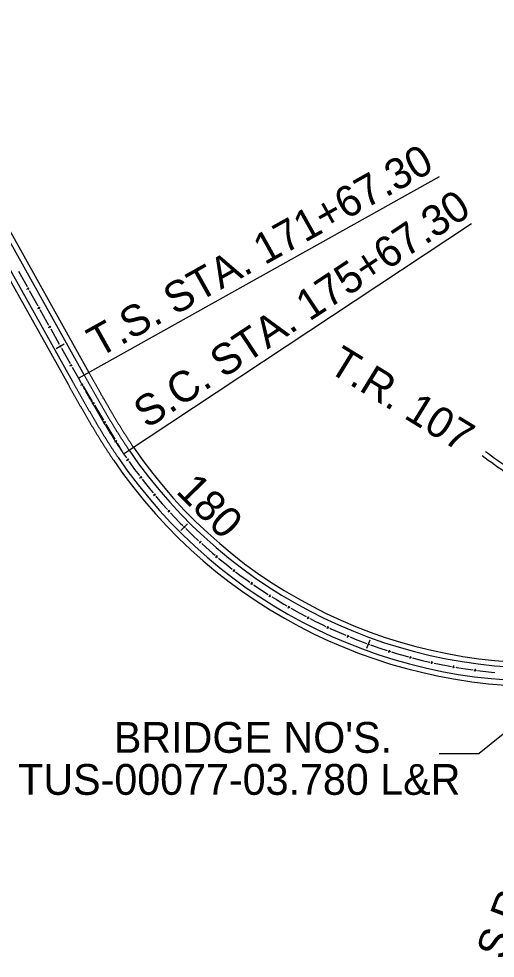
# Model space of a CAD drawing. Extents: x 0 to 34000, y 0 to 22000.
# Drawn here: x 23261 to 25424, y 4486 to 8756 of the extents above; entities that cross this region are included whole.
import ezdxf

# ---------------------------------------------------------------- set-up
doc = ezdxf.new("R2010")
doc.units = 0
doc.layers.add('Default', color=7, linetype='Continuous')
doc.layers.add('GE_P_CL_100', color=7, linetype='Continuous')

msp = doc.modelspace()

# ---------------------------------------------------------------- linework, layer by layer
at = {"layer": 'Default'}
for p, q in [((22679.2, 8756.5), (23578.5, 7148.4)), ((22605.9, 8715.4), (23505.2, 7107.4)), ((22658.3, 8744.7), (23557.6, 7136.7)), ((22585, 8703.7), (23484.3, 7095.7)), ((23297.9, 7527.2), (23308.4, 7533.1)), ((23346.7, 7440), (23357.2, 7445.8)), ((23395.5, 7352.7), (23406, 7358.5)), ((23430.6, 7257.7), (23467.2, 7278.2)), ((23493.2, 7178.1), (23503.6, 7184)), ((23542.9, 7091.2), (23553.2, 7097.3)), ((23594.2, 7005.4), (23604.5, 7011.5)), ((23645.5, 6919.5), (23655.8, 6925.7)), ((23696.8, 6833.7), (23707.1, 6839.9)), ((23750.3, 6748.7), (23760.1, 6755.7)), ((23809.6, 6667.9), (23819.1, 6675.2)), ((23872.4, 6589.8), (23881.6, 6597.5)), ((23938.5, 6514.3), (23947.2, 6522.5)), ((23943, 6518.3), (23943, 6518.3)), ((23996.5, 6430.7), (24026.9, 6461)), ((24012.2, 6446.2), (24012.2, 6446.2)), ((24080.4, 6372.7), (24088.4, 6381.6)), ((24155.7, 6306.7), (24163.4, 6315.9)), ((24233.9, 6244), (24241.2, 6253.5)), ((24314.8, 6184.8), (24321.7, 6194.6)), ((24398.2, 6129), (24404.6, 6139.2)), ((24483.9, 6077.1), (24489.9, 6087.5)), ((24571.9, 6029), (24577.4, 6039.6)), ((24661.7, 5984.6), (24666.8, 5995.4)), ((24753.6, 5944.3), (24758.1, 5955.4)), ((24842.1, 5894.7), (24856.3, 5933.3)), ((24942, 5875.8), (24945.5, 5887.3)), ((25038.2, 5847.9), (25041.3, 5859.5)), ((25135.6, 5824), (25138.2, 5835.8)), ((25233.9, 5804.6), (25236, 5816.4)), ((25333.1, 5789.3), (25334.5, 5801.2))]:
    msp.add_line(p, q, dxfattribs=at)
for points in [[(23259.2, 7608.7), (23298.3, 7538.9)], [(23300.7, 7534.5), (23305.6, 7525.8)], [(23308, 7521.5), (23347.1, 7451.6)], [(23349.5, 7447.3), (23354.4, 7438.5)], [(23356.8, 7434.2), (23395.9, 7364.4)], [(23398.3, 7360), (23403.2, 7351.3)], [(23405.6, 7346.9), (23444.7, 7277.1)], [(23447.1, 7272.7), (23452, 7264)], [(23454.5, 7259.6), (23493.5, 7189.8)], [(23495.9, 7185.4), (23500.8, 7176.7)], [(23503.3, 7172.3), (23531.4, 7122.1), (23542.9, 7102.9)], [(23545.4, 7098.6), (23550.6, 7090)], [(23553.1, 7085.7), (23594.2, 7017)], [(23596.8, 7012.7), (23601.9, 7004.2)], [(23604.5, 6999.9), (23645.5, 6931.2)], [(23648.1, 6926.9), (23653.2, 6918.3)], [(23655.8, 6914), (23696.9, 6845.4)], [(23699.4, 6841.1), (23704.6, 6832.5)], [(23707.1, 6828.2), (23736.6, 6778.9), (23740.7, 6772.8), (23749.4, 6760.4)], [(23752.3, 6756.3), (23758.1, 6748.1)], [(23761, 6744), (23763.7, 6740.2), (23786.9, 6707.8), (23808.3, 6679.5)], [(23811.3, 6675.5), (23817.4, 6667.6)], [(23820.5, 6663.7), (23835.6, 6644.1), (23860.6, 6613.1), (23870.6, 6601.3)], [(23873.8, 6597.5), (23880.2, 6589.8)], [(23883.4, 6586), (23886.4, 6582.4), (23912.5, 6552.2), (23936.1, 6525.8)], [(23939.4, 6522), (23946.2, 6514.8)], [(23949.7, 6511.1), (23966.5, 6493.1), (23994.3, 6464.1), (24005, 6453.4)], [(24008.5, 6449.8), (24016, 6442.3)], [(24019.1, 6439.2), (24022.5, 6435.8), (24051.3, 6408), (24077, 6384)], [(24080.7, 6380.6), (24088.1, 6373.8)], [(24091.8, 6370.5), (24110.1, 6353.9), (24140.1, 6327.5), (24151.9, 6317.7)], [(24155.7, 6314.5), (24163.4, 6308.1)], [(24167.2, 6304.9), (24170.8, 6301.9), (24201.8, 6276.6), (24229.6, 6254.8)], [(24233.6, 6251.8), (24241.5, 6245.7)], [(24245.5, 6242.7), (24265.3, 6227.7), (24297.6, 6204.2), (24310.1, 6195.4)], [(24314.2, 6192.6), (24322.3, 6186.8)], [(24326.4, 6183.9), (24330.3, 6181.2), (24363.3, 6158.8), (24393, 6139.5)], [(24397.2, 6136.8), (24405.6, 6131.5)], [(24409.9, 6128.8), (24430.7, 6115.8), (24465, 6094.9), (24478.2, 6087.3)], [(24482.6, 6084.8), (24491.2, 6079.8)], [(24495.6, 6077.3), (24499.6, 6075), (24534.6, 6055.4), (24565.7, 6038.9)], [(24570.2, 6036.6), (24579.1, 6032)], [(24583.5, 6029.7), (24605.5, 6018.4), (24641.3, 6000.8), (24655.2, 5994.3)], [(24659.7, 5992.1), (24668.8, 5987.9)], [(24673.3, 5985.8), (24677.6, 5983.8), (24714.2, 5967.6), (24746.6, 5953.7)], [(24751.2, 5951.7), (24760.5, 5948)], [(24765.1, 5946.1), (24788, 5936.8), (24825.2, 5922.3), (24839.6, 5917)], [(24844.3, 5915.3), (24853.7, 5911.9)], [(24858.4, 5910.1), (24862.8, 5908.5), (24900.7, 5895.6), (24934.2, 5884.6)], [(24938.9, 5883), (24948.5, 5880.1)], [(24953.3, 5878.6), (24976.8, 5871.3), (25015.4, 5860.3), (25030.1, 5856.3)], [(25034.9, 5855), (25044.6, 5852.4)], [(25049.4, 5851.1), (25053.9, 5849.8), (25092.6, 5840), (25127.1, 5832.1)], [(25132, 5831), (25141.8, 5828.8)], [(25146.6, 5827.8), (25170.9, 5822.5), (25210.1, 5814.9), (25225.1, 5812.3)], [(25230, 5811.4), (25239.9, 5809.7)], [(25244.8, 5808.8), (25249.4, 5808), (25289, 5801.5), (25323.9, 5796.6)], [(25328.8, 5795.9), (25338.7, 5794.7)], [(25343.7, 5794.1), (25368.2, 5791.1), (25408, 5786.6), (25423.2, 5785.3)]]:
    msp.add_lwpolyline(points, dxfattribs=at)
for radius, end in [(2261.8, 274.1413), (2237.8, 274.1413), (2345.8, 273.5817), (2321.8, 273.857)]:
    msp.add_arc((25631.8, 8067.6), radius, 214.2163, end, dxfattribs=at)
for points in [[(23557.6, 7136.7), (23560.6, 7131.3), (23563.6, 7126), (23566.6, 7120.6), (23569.6, 7115.2), (23572.6, 7109.9), (23575.6, 7104.5), (23578.6, 7099.1), (23581.6, 7093.8), (23584.6, 7088.4), (23587.6, 7083.1), (23590.6, 7077.7), (23593.6, 7072.4), (23596.6, 7067), (23599.7, 7061.7), (23602.7, 7056.3), (23605.7, 7051), (23608.7, 7045.7), (23611.8, 7040.3), (23614.8, 7035), (23617.8, 7029.7), (23620.9, 7024.3), (23623.9, 7019), (23626.9, 7013.7), (23630, 7008.4), (23633, 7003.1), (23636.1, 6997.8), (23639.2, 6992.5), (23642.2, 6987.2), (23645.3, 6981.9), (23648.4, 6976.6), (23651.5, 6971.3), (23654.6, 6966.1), (23657.7, 6960.8), (23660.8, 6955.5), (23663.9, 6950.3), (23667, 6945), (23670.1, 6939.8), (23673.3, 6934.5), (23676.4, 6929.3), (23679.6, 6924.1), (23682.7, 6918.8), (23685.9, 6913.6), (23689.1, 6908.4), (23692.3, 6903.2), (23695.4, 6898), (23698.6, 6892.8), (23701.9, 6887.6), (23705.1, 6882.5), (23708.3, 6877.3), (23711.5, 6872.1), (23714.8, 6867), (23718.1, 6861.9), (23721.3, 6856.7), (23724.6, 6851.6), (23727.9, 6846.5), (23731.2, 6841.4), (23734.5, 6836.2), (23737.8, 6831.2), (23741.2, 6826.1), (23744.5, 6821), (23747.9, 6815.9), (23751.3, 6810.9), (23754.6, 6805.8), (23758, 6800.8), (23761.4, 6795.8)], [(23578.5, 7148.4), (23581.5, 7143), (23584.5, 7137.7), (23587.5, 7132.3), (23590.5, 7127), (23593.5, 7121.6), (23596.5, 7116.2), (23599.5, 7110.9), (23602.5, 7105.5), (23605.5, 7100.2), (23608.5, 7094.8), (23611.5, 7089.5), (23614.5, 7084.1), (23617.6, 7078.8), (23620.6, 7073.5), (23623.6, 7068.1), (23626.6, 7062.8), (23629.6, 7057.5), (23632.6, 7052.2), (23635.6, 7046.9), (23638.7, 7041.6), (23641.7, 7036.2), (23644.7, 7030.9), (23647.8, 7025.7), (23650.8, 7020.4), (23653.8, 7015.1), (23656.9, 7009.8), (23659.9, 7004.5), (23663, 6999.3), (23666.1, 6994), (23669.1, 6988.7), (23672.2, 6983.5), (23675.3, 6978.2), (23678.4, 6973), (23681.4, 6967.7), (23684.5, 6962.5), (23687.6, 6957.3), (23690.8, 6952.1), (23693.9, 6946.9), (23697, 6941.7), (23700.1, 6936.5), (23703.3, 6931.3), (23706.4, 6926.1), (23709.6, 6920.9), (23712.7, 6915.8), (23715.9, 6910.6), (23719.1, 6905.4), (23722.3, 6900.3), (23725.4, 6895.2), (23728.6, 6890), (23731.9, 6884.9), (23735.1, 6879.8), (23738.3, 6874.7), (23741.6, 6869.6), (23744.8, 6864.5), (23748.1, 6859.5), (23751.3, 6854.4), (23754.6, 6849.3), (23757.9, 6844.3), (23761.2, 6839.3), (23764.5, 6834.2), (23767.9, 6829.2), (23771.2, 6824.2), (23774.6, 6819.2), (23777.9, 6814.2), (23781.3, 6809.3)], [(23484.3, 7095.7), (23487.3, 7090.3), (23490.3, 7085), (23493.3, 7079.6), (23496.3, 7074.2), (23499.3, 7068.8), (23502.3, 7063.4), (23505.3, 7058.1), (23508.3, 7052.7), (23511.4, 7047.3), (23514.4, 7041.9), (23517.4, 7036.5), (23520.4, 7031.1), (23523.5, 7025.8), (23526.5, 7020.4), (23529.6, 7015), (23532.6, 7009.6), (23535.7, 7004.2), (23538.7, 6998.8), (23541.8, 6993.4), (23544.8, 6988.1), (23547.9, 6982.7), (23551, 6977.3), (23554.1, 6971.9), (23557.2, 6966.5), (23560.3, 6961.1), (23563.4, 6955.8), (23566.5, 6950.4), (23569.6, 6945), (23572.7, 6939.6), (23575.9, 6934.3), (23579, 6928.9), (23582.2, 6923.5), (23585.3, 6918.2), (23588.5, 6912.8), (23591.6, 6907.4), (23594.8, 6902.1), (23598, 6896.7), (23601.2, 6891.4), (23604.4, 6886), (23607.7, 6880.7), (23610.9, 6875.3), (23614.1, 6870), (23617.4, 6864.7), (23620.6, 6859.3), (23623.9, 6854), (23627.2, 6848.7), (23630.5, 6843.3), (23633.8, 6838), (23637.1, 6832.7), (23640.4, 6827.4), (23643.8, 6822.1), (23647.1, 6816.8), (23650.5, 6811.5), (23653.9, 6806.2), (23657.3, 6801), (23660.7, 6795.7), (23664.1, 6790.4), (23667.5, 6785.2), (23671, 6779.9), (23674.5, 6774.7), (23677.9, 6769.4), (23681.4, 6764.2), (23684.9, 6759), (23688.4, 6753.7), (23692, 6748.5)], [(23505.2, 7107.4), (23508.2, 7102), (23511.2, 7096.7), (23514.2, 7091.3), (23517.2, 7085.9), (23520.2, 7080.6), (23523.2, 7075.2), (23526.3, 7069.8), (23529.3, 7064.4), (23532.3, 7059.1), (23535.3, 7053.7), (23538.3, 7048.3), (23541.4, 7042.9), (23544.4, 7037.6), (23547.4, 7032.2), (23550.5, 7026.8), (23553.5, 7021.4), (23556.5, 7016.1), (23559.6, 7010.7), (23562.6, 7005.3), (23565.7, 6999.9), (23568.8, 6994.6), (23571.8, 6989.2), (23574.9, 6983.9), (23578, 6978.5), (23581.1, 6973.1), (23584.2, 6967.8), (23587.3, 6962.4), (23590.4, 6957.1), (23593.5, 6951.7), (23596.6, 6946.4), (23599.7, 6941), (23602.8, 6935.7), (23606, 6930.3), (23609.1, 6925), (23612.3, 6919.7), (23615.5, 6914.3), (23618.6, 6909), (23621.8, 6903.7), (23625, 6898.4), (23628.2, 6893.1), (23631.4, 6887.8), (23634.6, 6882.5), (23637.9, 6877.2), (23641.1, 6871.9), (23644.4, 6866.6), (23647.6, 6861.3), (23650.9, 6856), (23654.2, 6850.7), (23657.5, 6845.5), (23660.8, 6840.2), (23664.1, 6834.9), (23667.4, 6829.7), (23670.7, 6824.4), (23674.1, 6819.2), (23677.5, 6814), (23680.8, 6808.7), (23684.2, 6803.5), (23687.6, 6798.3), (23691, 6793.1), (23694.5, 6787.9), (23697.9, 6782.7), (23701.4, 6777.5), (23704.8, 6772.4), (23708.3, 6767.2), (23711.8, 6762)], [(23531.4, 7122.1), (23534.4, 7116.7), (23537.4, 7111.3), (23540.4, 7105.9), (23543.4, 7100.6), (23546.4, 7095.2), (23549.4, 7089.8), (23552.4, 7084.5), (23555.4, 7079.1), (23558.4, 7073.7), (23561.5, 7068.4), (23564.5, 7063), (23567.5, 7057.6), (23570.5, 7052.3), (23573.5, 7046.9), (23576.6, 7041.6), (23579.6, 7036.2), (23582.6, 7030.9), (23585.7, 7025.5), (23588.7, 7020.2), (23591.8, 7014.8), (23594.8, 7009.5), (23597.9, 7004.1), (23600.9, 6998.8), (23604, 6993.4), (23607.1, 6988.1), (23610.1, 6982.8), (23613.2, 6977.5), (23616.3, 6972.1), (23619.4, 6966.8), (23622.5, 6961.5), (23625.6, 6956.2), (23628.7, 6950.9), (23631.8, 6945.6), (23635, 6940.3), (23638.1, 6935), (23641.2, 6929.7), (23644.4, 6924.4), (23647.5, 6919.1), (23650.7, 6913.8), (23653.9, 6908.6), (23657.1, 6903.3), (23660.3, 6898), (23663.5, 6892.8), (23666.7, 6887.5), (23669.9, 6882.3), (23673.1, 6877.1), (23676.4, 6871.8), (23679.6, 6866.6), (23682.9, 6861.4), (23686.2, 6856.2), (23689.4, 6851), (23692.7, 6845.8), (23696, 6840.6), (23699.4, 6835.4), (23702.7, 6830.2), (23706, 6825), (23709.4, 6819.9), (23712.7, 6814.7), (23716.1, 6809.6), (23719.5, 6804.4), (23722.9, 6799.3), (23726.3, 6794.2), (23729.7, 6789.1), (23733.2, 6784), (23736.6, 6778.9)], [(26192.3, 6596.8), (26175.7, 6598.4), (26119.8, 6605.9), (26063.9, 6599.1), (26035.2, 6580.5), (26005.8, 6562.4), (25957.9, 6553.3), (25768.1, 6559.3), (25598, 6618.1), (25364.7, 6769.6)], [(26239.1, 6618.9), (26219.5, 6618.3), (26178.5, 6622.2), (26119.9, 6630), (26055.5, 6622.2), (26022.3, 6600.8), (25997, 6585.2), (25956, 6577.4), (25772.5, 6583.2), (25608.6, 6639.8), (25380.3, 6788.1)]]:
    msp.add_spline(points, degree=3, dxfattribs=at)
at = {"layer": 'GE_P_CL_100'}
for p, q in [((23531.4, 7122.1), (25171.2, 8039.1)), ((23736.6, 6778.9), (25317, 7825.2)), ((25802.5, 5779.9), (25351.3, 5416.6)), ((25169.1, 5416.6), (25351.3, 5416.6))]:
    msp.add_line(p, q, dxfattribs=at)

# ---------------------------------------------------------------- texts
for s, rotation, p in [('T.S. STA. 171+67.30', 29.2166, (23623.8, 7213.9)), ('S.C. STA. 175+67.30', 33.5066, (23843.1, 6890.5)), ('T.R. 107', 328.4259, (24658.9, 7156.7)), ('180', 314.8013, (23970, 6604.6)), ('S.R. 258', 69.1419, (25465.2, 4471.6))]:
    msp.add_text(s, height=140, rotation=rotation, dxfattribs=at).set_placement(p)
for s, p in [("BRIDGE NO'S.", (23692.7, 5419.6)), ('TUS-00077-03.780 L&R', (23257.9, 5228.6))]:
    msp.add_text(s, height=140, dxfattribs=at).set_placement(p)

doc.saveas('drawing.dxf')
